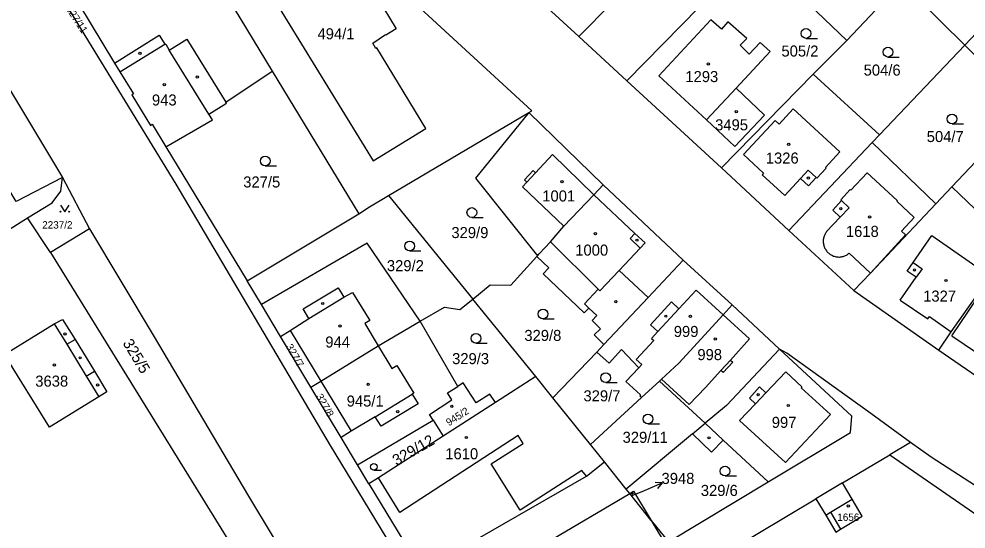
# Model space of a CAD drawing. Extents: x -679220 to -673243, y -1075091 to -1066557.
# Drawn here: x -675968.3 to -675822.7, y -1072251.7 to -1072173.3 of the extents above; entities that cross this region are included whole.
import ezdxf

# ---------------------------------------------------------------- set-up
doc = ezdxf.new("R2010")
doc.units = 0
for name, color, linetype in [('Hranice parcel', 7, 'Continuous'), ('Parcelní čísla', 7, 'Continuous'), ('Pop  PČ popisy', 7, 'Continuous'), ('Vnitřní kresba', 7, 'Continuous'), ('Značky budov', 7, 'Continuous'), ('Značky kultur', 7, 'Continuous')]:
    doc.layers.add(name, color=color, linetype=linetype)

msp = doc.modelspace()

# ---------------------------------------------------------------- linework, layer by layer
at = {"layer": 'Hranice parcel'}
for p, q in [((-675822.87, -1072177.31), (-675804.14, -1072157.36)), ((-675841, -1072176.55), (-675855.42, -1072162.79)), ((-675938.85, -1072165.67), (-675929.38, -1072181.3)), ((-675832.59, -1072167.65), (-675841, -1072176.55)), ((-675832.59, -1072167.65), (-675822.87, -1072177.31)), ((-675882.2, -1072175.96), (-675877.17, -1072170.82)), ((-675882.2, -1072175.96), (-675874.86, -1072182.77)), ((-675841, -1072176.55), (-675846.2, -1072181.74)), ((-675835.96, -1072191.08), (-675822.87, -1072177.31)), ((-675822.87, -1072177.31), (-675813.23, -1072186.76)), ((-675929.38, -1072181.3), (-675916.07, -1072203.21)), ((-675846.2, -1072181.74), (-675860.28, -1072196.18)), ((-675835.96, -1072191.08), (-675846.2, -1072181.74)), ((-675874.86, -1072182.77), (-675860.28, -1072196.18)), ((-675862.57, -1072188.76), (-675858.05, -1072183.92)), ((-675813.23, -1072186.76), (-675824.84, -1072199.06)), ((-675911.51, -1072200.39), (-675889.92, -1072187.67)), ((-675878.49, -1072198.75), (-675889.92, -1072187.67)), ((-675837.1, -1072192.28), (-675835.96, -1072191.08)), ((-675849.94, -1072205.78), (-675837.1, -1072192.28)), ((-675827.32, -1072201.69), (-675837.1, -1072192.28)), ((-675945.71, -1072192.93), (-675933.22, -1072213.55)), ((-675860.28, -1072196.18), (-675849.94, -1072205.78)), ((-675961.64, -1072197.66), (-675957.46, -1072205.54)), ((-675866.16, -1072210.38), (-675878.49, -1072198.75)), ((-675824.84, -1072199.06), (-675827.32, -1072201.69)), ((-675911.51, -1072200.39), (-675898.53, -1072216.33)), ((-676000.77, -1072224.76), (-675966.99, -1072203.87)), ((-675963.46, -1072209.2), (-675966.99, -1072203.87)), ((-675933.22, -1072213.55), (-675916.07, -1072203.21)), ((-675957.46, -1072205.54), (-675963.46, -1072209.2)), ((-675849.94, -1072205.78), (-675839.95, -1072215.04)), ((-675963.46, -1072209.2), (-675930.36, -1072262.74)), ((-675888.7, -1072209.8), (-675888.59, -1072209.68)), ((-675888.7, -1072209.8), (-675886.82, -1072211.51)), ((-675858.63, -1072217.23), (-675866.16, -1072210.38)), ((-675931.04, -1072217.19), (-675933.22, -1072213.55)), ((-675839.95, -1072215.04), (-675826.88, -1072224.19)), ((-675928.1, -1072222.1), (-675931.04, -1072217.19)), ((-675888.81, -1072228.27), (-675898.53, -1072216.33)), ((-675851.38, -1072224.03), (-675858.63, -1072217.23)), ((-675900.85, -1072229.77), (-675906.6, -1072219.76)), ((-675923.45, -1072229.88), (-675928.1, -1072222.1)), ((-675879.87, -1072221.83), (-675878.36, -1072223.31)), ((-675879.46, -1072224.48), (-675886.22, -1072231.53)), ((-675878.36, -1072223.31), (-675879.46, -1072224.48)), ((-675826.88, -1072224.19), (-675815.27, -1072232.21)), ((-675923.45, -1072229.88), (-675921.9, -1072228.94)), ((-675888.81, -1072228.27), (-675895.05, -1072232.27)), ((-675886.22, -1072231.53), (-675888.81, -1072228.27)), ((-675869.79, -1072228.94), (-675872.57, -1072231.49)), ((-675862.79, -1072235.44), (-675869.79, -1072228.94)), ((-675918.79, -1072237.63), (-675923.45, -1072229.88)), ((-675880.45, -1072238.71), (-675886.22, -1072231.53)), ((-675872.57, -1072231.49), (-675880.45, -1072238.71)), ((-675872.85, -1072231.2), (-675872.57, -1072231.49)), ((-675895.05, -1072232.27), (-675903.06, -1072237.41)), ((-675916.25, -1072241.85), (-675904.63, -1072234.97)), ((-675904.63, -1072234.97), (-675903.06, -1072237.41)), ((-675864.76, -1072237.08), (-675862.79, -1072235.44)), ((-675916.25, -1072241.85), (-675918.79, -1072237.63)), ((-675864.76, -1072237.08), (-675874.93, -1072245.59)), ((-675878.25, -1072241.39), (-675880.45, -1072238.71)), ((-675831.19, -1072238.38), (-675834.37, -1072240.28)), ((-675841.66, -1072244.62), (-675834.37, -1072240.28)), ((-675834.37, -1072240.28), (-675799.8, -1072264.22)), ((-675914.5, -1072244.76), (-675916.25, -1072241.85)), ((-675874.93, -1072245.59), (-675878.25, -1072241.39)), ((-675914.5, -1072244.76), (-675906.36, -1072258.16)), ((-675868.44, -1072253.67), (-675853.09, -1072244.45)), ((-675841.66, -1072244.62), (-675845.76, -1072247.06)), ((-675874.39, -1072246.25), (-675874.93, -1072245.59)), ((-675871.11, -1072250.38), (-675874.39, -1072246.25)), ((-675895.24, -1072276.53), (-675845.76, -1072247.06)), ((-675871.11, -1072250.38), (-675868.44, -1072253.67)), ((-675871.11, -1072250.38), (-675868.96, -1072253.98))]:
    msp.add_line(p, q, dxfattribs=at)
for points in [[(-675990.34, -1072122.74), (-675965.06, -1072164.5), (-675944.22, -1072198.66), (-675920.45, -1072238.88), (-675899.68, -1072273.04), (-675879.13, -1072306.74), (-675849.47, -1072355.79), (-675790.19, -1072454.14)], [(-676002.04, -1072130.35), (-675984.64, -1072159.26), (-675978.83, -1072168.99), (-675961.64, -1072197.66)], [(-675961.64, -1072197.66), (-675968.73, -1072201.32), (-676008.59, -1072134.94)], [(-675889.92, -1072187.67), (-675889.47, -1072187.41), (-675911.07, -1072167.47), (-675923.12, -1072156.21)], [(-675895.7, -1072163.48), (-675887.06, -1072171.53), (-675882.2, -1072175.96)], [(-675855.42, -1072162.79), (-675863.71, -1072171.45), (-675874.86, -1072182.77)], [(-675959.18, -1072170.89), (-675953.64, -1072180.04), (-675952.8, -1072181.4), (-675950.72, -1072184.79), (-675950.97, -1072184.94), (-675948.1, -1072189.62), (-675947.84, -1072189.46), (-675945.71, -1072192.93)], [(-675858.05, -1072183.92), (-675852.79, -1072178.27), (-675854.31, -1072176.9), (-675856.05, -1072178.66), (-675857.43, -1072177.29), (-675856.4, -1072176.26), (-675859.3, -1072173.68), (-675860.3, -1072174.81), (-675861.92, -1072173.38), (-675869.92, -1072182), (-675862.57, -1072188.76)], [(-675945.71, -1072192.93), (-675938.56, -1072188.75), (-675939.11, -1072187.9), (-675936.39, -1072186.2), (-675936.49, -1072186.05), (-675929.38, -1072181.3)], [(-675858.05, -1072183.92), (-675853.68, -1072188.04), (-675858.25, -1072192.88), (-675862.57, -1072188.76)], [(-675889.92, -1072187.67), (-675898.1, -1072197.76), (-675888.59, -1072209.68)], [(-675966.99, -1072203.87), (-675963.2, -1072201.53), (-675961.87, -1072199.73), (-675961.64, -1072197.66)], [(-675888.59, -1072209.68), (-675888.34, -1072209.4), (-675886.57, -1072207.52), (-675884.51, -1072205.15), (-675879.91, -1072200.31), (-675878.49, -1072198.75)], [(-675811.2, -1072204.98), (-675812.84, -1072203.4), (-675816.48, -1072207.05), (-675824.84, -1072199.06)], [(-675916.07, -1072203.21), (-675914.43, -1072202.13), (-675911.51, -1072200.39)], [(-675827.32, -1072201.69), (-675837.36, -1072212.33), (-675839.95, -1072215.04)], [(-675957.46, -1072205.54), (-675947.66, -1072221.89), (-675933.02, -1072246.64), (-675925.29, -1072259.54)], [(-675906.6, -1072219.76), (-675914.77, -1072207.74), (-675931.04, -1072217.19)], [(-675826.88, -1072224.19), (-675824.97, -1072221.37), (-675819.4, -1072213.52), (-675817.52, -1072211.55), (-675814.73, -1072208.65)], [(-675898.53, -1072216.33), (-675895.85, -1072214.13), (-675892.66, -1072214.19), (-675888.7, -1072209.8)], [(-675886.82, -1072211.51), (-675887.68, -1072212.44), (-675881.42, -1072218.46), (-675880.68, -1072217.74), (-675879.45, -1072218.89), (-675880.16, -1072219.66), (-675878.91, -1072220.9), (-675879.87, -1072221.83)], [(-675866.16, -1072210.38), (-675871.56, -1072216.1), (-675878.36, -1072223.31)], [(-675906.6, -1072219.76), (-675902.88, -1072217.59), (-675900.52, -1072217.95), (-675898.53, -1072216.33)], [(-675858.63, -1072217.23), (-675860.02, -1072218.78), (-675866.83, -1072226.22), (-675869.49, -1072228.66), (-675869.79, -1072228.94)], [(-675963.64, -1072236.05), (-675970.54, -1072224.86), (-675962.89, -1072220.17), (-675961.65, -1072219.46), (-675959.69, -1072222.56), (-675956.72, -1072227.41), (-675954.82, -1072230.61), (-675956.06, -1072231.38), (-675963.64, -1072236.05)], [(-675921.9, -1072228.94), (-675913.06, -1072223.55), (-675906.6, -1072219.76)], [(-675928.1, -1072222.1), (-675926.62, -1072221.15), (-675921.9, -1072228.94)], [(-675879.46, -1072224.48), (-675877.58, -1072226.19), (-675875.64, -1072224.11), (-675873, -1072226.89), (-675874.99, -1072229.03)], [(-675851.38, -1072224.03), (-675859.52, -1072232.7), (-675862.79, -1072235.44)], [(-675853.09, -1072244.45), (-675840.42, -1072236.85), (-675840.26, -1072234.34), (-675851.38, -1072224.03)], [(-675831.19, -1072238.38), (-675837.34, -1072233.96), (-675850.24, -1072224.64), (-675851.38, -1072224.03)], [(-675921.9, -1072228.94), (-675917.21, -1072236.67), (-675918.79, -1072237.63)], [(-675874.99, -1072229.03), (-675872.73, -1072231.08), (-675872.85, -1072231.2)], [(-675904.63, -1072234.97), (-675905.21, -1072234.07), (-675901.74, -1072231.84), (-675902.42, -1072230.77), (-675900.85, -1072229.77)], [(-675895.05, -1072232.27), (-675895.9, -1072230.94), (-675898.02, -1072232.3), (-675900, -1072229.22), (-675900.85, -1072229.77)], [(-675903.06, -1072237.41), (-675913.02, -1072243.81), (-675914.5, -1072244.76)], [(-675853.09, -1072244.45), (-675860.01, -1072238.02), (-675861.81, -1072239.9), (-675864.76, -1072237.08)], [(-675675.24, -1072344.8), (-675677.06, -1072343.56), (-675675.65, -1072341.45), (-675809.62, -1072248.86), (-675810.47, -1072252.39), (-675814.41, -1072249.48), (-675828.02, -1072240.66), (-675831.19, -1072238.38)], [(-675906.36, -1072258.16), (-675881.04, -1072243.59), (-675878.25, -1072241.39)], [(-675845.76, -1072247.06), (-675844.26, -1072249.58), (-675842.72, -1072252.17), (-675841.96, -1072251.71), (-675838.63, -1072249.72), (-675840.17, -1072247.13), (-675841.66, -1072244.62)], [(-675891.17, -1072267.15), (-675896.13, -1072258.79), (-675887.39, -1072253.59), (-675887.24, -1072253.85), (-675874.39, -1072246.25)], [(-675874.39, -1072246.25), (-675873.79, -1072245.89), (-675871.11, -1072250.38)]]:
    msp.add_lwpolyline(points, dxfattribs=at)
at = {"layer": 'Pop  PČ popisy'}
for p, q in [((-675872.14, -1072245.77), (-675869.38, -1072244.6)), ((-675869.38, -1072244.6), (-675870.49, -1072244.53)), ((-675869.38, -1072244.6), (-675870.1, -1072245.45)), ((-675874.01, -1072246.56), (-675872.14, -1072245.77))]:
    msp.add_line(p, q, dxfattribs=at)
at = {"layer": 'Vnitřní kresba'}
for p, q in [((-675933.75, -1072162.6), (-675913.85, -1072195.08)), ((-675913.98, -1072168.74), (-675910.32, -1072174.79)), ((-675910.32, -1072174.79), (-675911.92, -1072175.76)), ((-675953.64, -1072180.04), (-675946.76, -1072175.76)), ((-675946.76, -1072175.76), (-675945.91, -1072177.12)), ((-675945.24, -1072178.06), (-675942.52, -1072176.37)), ((-675942.52, -1072176.37), (-675936.49, -1072186.05)), ((-675913.91, -1072177), (-675911.97, -1072175.67)), ((-675911.97, -1072175.67), (-675911.92, -1072175.76)), ((-675952.8, -1072181.4), (-675945.91, -1072177.12)), ((-675945.91, -1072177.12), (-675945.75, -1072177.12)), ((-675945.75, -1072177.12), (-675945.24, -1072178.06)), ((-675939.11, -1072187.9), (-675945.24, -1072178.06)), ((-675913.42, -1072177.8), (-675913.91, -1072177)), ((-675913.29, -1072177.72), (-675913.42, -1072177.8)), ((-675905.74, -1072190.13), (-675913.29, -1072177.72)), ((-675851.43, -1072189.43), (-675849.24, -1072187.07)), ((-675849.24, -1072187.07), (-675842.08, -1072193.69)), ((-675856.92, -1072194.12), (-675852.05, -1072188.85)), ((-675852.05, -1072188.85), (-675851.43, -1072189.43)), ((-675913.85, -1072195.08), (-675905.74, -1072190.13)), ((-675844.29, -1072196.09), (-675842.08, -1072193.69)), ((-675888.88, -1072196.9), (-675886.26, -1072194.1)), ((-675886.26, -1072194.1), (-675879.91, -1072200.31)), ((-675856.92, -1072194.12), (-675853.82, -1072197)), ((-675890.59, -1072198.01), (-675889.24, -1072196.57)), ((-675888.88, -1072196.9), (-675890.23, -1072198.35)), ((-675889.24, -1072196.57), (-675888.88, -1072196.9)), ((-675853.82, -1072197), (-675854.02, -1072197.22)), ((-675848.12, -1072197.78), (-675846.94, -1072196.5)), ((-675846.94, -1072196.5), (-675845.71, -1072197.62)), ((-675845.6, -1072197.73), (-675844.18, -1072196.19)), ((-675844.18, -1072196.19), (-675844.29, -1072196.09)), ((-675840.37, -1072199.59), (-675837.87, -1072196.94)), ((-675837.87, -1072196.94), (-675833.24, -1072201.19)), ((-675890.9, -1072199.07), (-675890.23, -1072198.35)), ((-675890.23, -1072198.35), (-675890.59, -1072198.01)), ((-675854.02, -1072197.22), (-675850.56, -1072200.43)), ((-675850.56, -1072200.43), (-675848.12, -1072197.78)), ((-675848.12, -1072197.78), (-675846.89, -1072198.91)), ((-675846.89, -1072198.91), (-675845.71, -1072197.62)), ((-675845.71, -1072197.62), (-675845.6, -1072197.73)), ((-675884.51, -1072205.15), (-675890.9, -1072199.07)), ((-675841.95, -1072201.09), (-675840.48, -1072199.49)), ((-675840.48, -1072199.49), (-675840.37, -1072199.59)), ((-675873.6, -1072206.25), (-675879.91, -1072200.31)), ((-675843.17, -1072202.65), (-675841.84, -1072201.2)), ((-675841.84, -1072201.2), (-675841.95, -1072201.09)), ((-675841.84, -1072201.2), (-675840.65, -1072202.29)), ((-675833.24, -1072201.19), (-675833.34, -1072201.3)), ((-675833.34, -1072201.3), (-675830.65, -1072203.77)), ((-675842.02, -1072203.75), (-675843.17, -1072202.65)), ((-675840.65, -1072202.29), (-675842.02, -1072203.75)), ((-675844.11, -1072205.97), (-675842.02, -1072203.75)), ((-675830.65, -1072203.77), (-675832.61, -1072205.9)), ((-675873.6, -1072206.25), (-675874.35, -1072207.04)), ((-675874.35, -1072207.04), (-675872.78, -1072208.52)), ((-675872.02, -1072207.71), (-675873.6, -1072206.25)), ((-675831.98, -1072206.48), (-675837.36, -1072212.33)), ((-675832.61, -1072205.9), (-675831.98, -1072206.48)), ((-675830.81, -1072210.71), (-675827.91, -1072206.55)), ((-675827.91, -1072206.55), (-675818.97, -1072212.84)), ((-675886.57, -1072207.52), (-675879.24, -1072214.82)), ((-675876.02, -1072211.95), (-675872.78, -1072208.52)), ((-675872.78, -1072208.52), (-675872.02, -1072207.71)), ((-675840.63, -1072209.26), (-675837.36, -1072212.33)), ((-675831.71, -1072212.03), (-675830.81, -1072210.71)), ((-675830.81, -1072210.71), (-675829.44, -1072211.67)), ((-675878.98, -1072215.06), (-675876.02, -1072211.95)), ((-675876.02, -1072211.95), (-675871.56, -1072216.1)), ((-675832.81, -1072216.51), (-675830.35, -1072212.98)), ((-675830.35, -1072212.98), (-675831.71, -1072212.03)), ((-675829.44, -1072211.67), (-675830.35, -1072212.98)), ((-675824.84, -1072221.97), (-675819.63, -1072214.25)), ((-675924.63, -1072217.85), (-675919.22, -1072214.61)), ((-675919.22, -1072214.61), (-675918.35, -1072216.07)), ((-675918.35, -1072216.07), (-675917.04, -1072215.34)), ((-675917.04, -1072215.34), (-675914.38, -1072219.62)), ((-675879.24, -1072214.82), (-675881.37, -1072217.07)), ((-675879.24, -1072214.82), (-675878.98, -1072215.06)), ((-675864.19, -1072214.97), (-675866.83, -1072217.83)), ((-675860.02, -1072218.78), (-675864.19, -1072214.97)), ((-675923.76, -1072219.31), (-675918.35, -1072216.07)), ((-675881.37, -1072217.07), (-675880.68, -1072217.74)), ((-675867.97, -1072216.77), (-675871.21, -1072220.3)), ((-675866.83, -1072217.83), (-675867.97, -1072216.77)), ((-675832.81, -1072216.51), (-675828.54, -1072219.38)), ((-675923.76, -1072219.31), (-675924.63, -1072217.85)), ((-675870.08, -1072221.35), (-675866.83, -1072217.83)), ((-675860.02, -1072218.78), (-675855.97, -1072222.48)), ((-675962.89, -1072220.17), (-675960.97, -1072223.3)), ((-675926.62, -1072221.15), (-675923.76, -1072219.31)), ((-675914.38, -1072219.62), (-675915.15, -1072220.09)), ((-675915.15, -1072220.09), (-675913.06, -1072223.55)), ((-675871.21, -1072220.3), (-675870.08, -1072221.35)), ((-675828.54, -1072219.38), (-675828.29, -1072219.03)), ((-675828.29, -1072219.03), (-675824.97, -1072221.37)), ((-675870.08, -1072221.35), (-675871.03, -1072222.38)), ((-675960.97, -1072223.3), (-675959.69, -1072222.56)), ((-675870.69, -1072222.69), (-675873.39, -1072225.62)), ((-675871.03, -1072222.38), (-675870.69, -1072222.69)), ((-675855.97, -1072222.48), (-675858.91, -1072225.72)), ((-675824.84, -1072221.97), (-675816.78, -1072227.53)), ((-675960.97, -1072223.3), (-675958.01, -1072228.2)), ((-675913.06, -1072223.55), (-675910.97, -1072227.02)), ((-675873.39, -1072225.62), (-675872.55, -1072226.4)), ((-675860.37, -1072227.33), (-675858.91, -1072225.72)), ((-675858.55, -1072226.04), (-675860.01, -1072227.65)), ((-675858.91, -1072225.72), (-675858.55, -1072226.04)), ((-675958.01, -1072228.2), (-675956.72, -1072227.41)), ((-675910.97, -1072227.02), (-675910.2, -1072226.55)), ((-675910.2, -1072226.55), (-675907.61, -1072230.83)), ((-675872.55, -1072226.4), (-675873, -1072226.89)), ((-675860.37, -1072227.33), (-675862.74, -1072229.95)), ((-675860.01, -1072227.65), (-675860.37, -1072227.33)), ((-675853.48, -1072230.78), (-675850.4, -1072227.52)), ((-675850.4, -1072227.52), (-675847.93, -1072229.86)), ((-675958.01, -1072228.2), (-675956.06, -1072231.38)), ((-675865.24, -1072232.55), (-675869.49, -1072228.66)), ((-675862.74, -1072229.95), (-675865.24, -1072232.55)), ((-675855.98, -1072231.6), (-675854.46, -1072229.85)), ((-675854.46, -1072229.85), (-675853.48, -1072230.78)), ((-675847.93, -1072229.86), (-675848.03, -1072229.97)), ((-675848.03, -1072229.97), (-675843.54, -1072234.08)), ((-675913.52, -1072234.43), (-675907.84, -1072230.97)), ((-675907.61, -1072230.83), (-675907.84, -1072230.97)), ((-675907.84, -1072230.97), (-675906.95, -1072232.44)), ((-675855.06, -1072232.46), (-675855.98, -1072231.6)), ((-675853.48, -1072230.78), (-675855.06, -1072232.46)), ((-675906.95, -1072232.44), (-675912.63, -1072235.89)), ((-675857.49, -1072235.03), (-675855.06, -1072232.46)), ((-675913.52, -1072234.43), (-675917.21, -1072236.67)), ((-675912.63, -1072235.89), (-675913.52, -1072234.43)), ((-675843.54, -1072234.08), (-675850.42, -1072241.5)), ((-675862.79, -1072235.44), (-675860.01, -1072238.02)), ((-675850.42, -1072241.5), (-675857.49, -1072235.03)), ((-675891.55, -1072237.31), (-675909.77, -1072249.14)), ((-675890.77, -1072238.53), (-675891.55, -1072237.31)), ((-675895.69, -1072241.69), (-675890.77, -1072238.53)), ((-675891.22, -1072248.79), (-675895.69, -1072241.69)), ((-675881.77, -1072242.69), (-675891.22, -1072248.79)), ((-675881.04, -1072243.59), (-675881.77, -1072242.69)), ((-675909.77, -1072249.14), (-675913.02, -1072243.81)), ((-675843.5, -1072249.12), (-675840.17, -1072247.13)), ((-675844.26, -1072249.58), (-675843.5, -1072249.12)), ((-675843.5, -1072249.12), (-675841.96, -1072251.71))]:
    msp.add_line(p, q, dxfattribs=at)
msp.add_lwpolyline([(-675844.11, -1072205.97), (-675844.19, -1072206.08), (-675844.27, -1072206.19), (-675844.34, -1072206.31), (-675844.4, -1072206.44), (-675844.46, -1072206.56), (-675844.5, -1072206.69), (-675844.54, -1072206.82), (-675844.58, -1072206.95), (-675844.6, -1072207.09), (-675844.62, -1072207.22), (-675844.63, -1072207.36), (-675844.63, -1072207.5), (-675844.62, -1072207.64), (-675844.61, -1072207.77), (-675844.59, -1072207.91), (-675844.56, -1072208.04), (-675844.52, -1072208.17), (-675844.48, -1072208.3), (-675844.43, -1072208.43), (-675844.37, -1072208.56), (-675844.3, -1072208.68), (-675844.23, -1072208.79), (-675844.15, -1072208.9), (-675844.07, -1072209.01), (-675843.98, -1072209.11), (-675843.88, -1072209.21), (-675843.78, -1072209.3), (-675843.67, -1072209.39), (-675843.56, -1072209.47), (-675843.44, -1072209.54), (-675843.32, -1072209.6), (-675843.2, -1072209.66), (-675843.07, -1072209.72), (-675842.94, -1072209.76), (-675842.81, -1072209.8), (-675842.67, -1072209.83), (-675842.54, -1072209.85), (-675842.4, -1072209.86), (-675842.26, -1072209.87), (-675842.13, -1072209.87), (-675841.99, -1072209.86), (-675841.85, -1072209.84), (-675841.72, -1072209.81), (-675841.59, -1072209.78), (-675841.46, -1072209.74), (-675841.33, -1072209.69), (-675841.2, -1072209.64), (-675841.08, -1072209.57), (-675840.96, -1072209.51), (-675840.85, -1072209.43), (-675840.73, -1072209.35), (-675840.63, -1072209.26)], dxfattribs=at)
at = {"layer": 'Značky budov'}
for centre, radius in [((-675949.71, -1072178.54), 0.175), ((-675862.3, -1072180.18), 0.175), ((-675940.91, -1072182.2), 0.175), ((-675945.97, -1072183.37), 0.175), ((-675858.01, -1072187.5), 0.175), ((-675849.95, -1072192.56), 0.175), ((-675884.82, -1072198.27), 0.175), ((-675846.91, -1072197.72), 0.175), ((-675841.93, -1072202.45), 0.175), ((-675837.5, -1072203.71), 0.175), ((-675879.67, -1072206.28), 0.175), ((-675873.29, -1072207.28), 0.175), ((-675830.6, -1072211.86), 0.175), ((-675825.75, -1072213.48), 0.175), ((-675921.61, -1072217.02), 0.175), ((-675876.53, -1072216.75), 0.175), ((-675868.84, -1072218.97), 0.175), ((-675865.06, -1072219.01), 0.175), ((-675918.96, -1072220.48), 0.175), ((-675961.22, -1072221.7), 0.175), ((-675861.23, -1072222.49), 0.175), ((-675958.91, -1072225.38), 0.175), ((-675962.88, -1072226.46), 0.175), ((-675956.22, -1072229.55), 0.175), ((-675914.62, -1072229.46), 0.175), ((-675854.64, -1072231.03), 0.175), ((-675901.75, -1072232.84), 0.175), ((-675850.02, -1072232.71), 0.175), ((-675910.06, -1072233.65), 0.175), ((-675899.5, -1072237.63), 0.175), ((-675862.19, -1072237.68), 0.175), ((-675873.98, -1072246.24), 0.117), ((-675840.79, -1072248.16), 0.175)]:
    msp.add_circle(centre, radius, dxfattribs=at)
at = {"layer": 'Značky kultur'}
for p, q in [((-675847.28, -1072176.24), (-675845.53, -1072176.24)), ((-675834.69, -1072179.11), (-675832.94, -1072179.11)), ((-675824.83, -1072189.39), (-675823.08, -1072189.39)), ((-675930.45, -1072195.84), (-675928.7, -1072195.84)), ((-675898.67, -1072203.78), (-675896.92, -1072203.78)), ((-675908.25, -1072208.93), (-675906.5, -1072208.93)), ((-675887.74, -1072219.38), (-675885.99, -1072219.38)), ((-675898.05, -1072223.13), (-675896.3, -1072223.13)), ((-675878.09, -1072229.19), (-675876.34, -1072229.19)), ((-675871.59, -1072235.54), (-675869.84, -1072235.54)), ((-675913.73, -1072242.64), (-675912.56, -1072242.64)), ((-675859.74, -1072243.55), (-675857.99, -1072243.55))]:
    msp.add_line(p, q, dxfattribs=at)
msp.add_lwpolyline([(-675961.92, -1072201.89), (-675961.25, -1072202.9), (-675960.58, -1072201.89)], dxfattribs=at)
for centre, radius in [((-675847.28, -1072175.49), 0.75), ((-675834.69, -1072178.36), 0.75), ((-675824.83, -1072188.64), 0.75), ((-675930.45, -1072195.09), 0.75), ((-675961.92, -1072202.9), 0.067), ((-675960.58, -1072202.9), 0.067), ((-675898.67, -1072203.03), 0.75), ((-675908.25, -1072208.18), 0.75), ((-675887.74, -1072218.63), 0.75), ((-675898.05, -1072222.38), 0.75), ((-675878.09, -1072228.44), 0.75), ((-675871.59, -1072234.79), 0.75), ((-675913.74, -1072242.14), 0.502), ((-675859.74, -1072242.8), 0.75)]:
    msp.add_circle(centre, radius, dxfattribs=at)

# ---------------------------------------------------------------- texts
at = {"layer": 'Parcelní čísla'}
for s, height, rotation, p in [('327/11', 1.14, 303, (-675961.17, -1072171.68)), ('325/5', 1.7, 301, (-675952.43, -1072223.09)), ('327/7', 1.14, 300, (-675927.32, -1072223.65)), ('327/8', 1.14, 300, (-675922.7, -1072231.3)), ('945/2', 1.14, 33, (-675902.19, -1072235.92)), ('329/12', 1.7, 30, (-675910.27, -1072242.03))]:
    msp.add_text(s, height=height, rotation=rotation, dxfattribs=at).set_placement(p)
for s, height, p in [('494/1', 1.7, (-675922.41, -1072176.39)), ('505/2', 1.7, (-675851.06, -1072179.04)), ('504/6', 1.7, (-675838.42, -1072181.97)), ('1293', 1.7, (-675865.84, -1072182.97)), ('943', 1.7, (-675947.87, -1072186.57)), ('3495', 1.7, (-675861.26, -1072190.39)), ('504/7', 1.7, (-675828.72, -1072192.19)), ('1326', 1.7, (-675853.47, -1072195.5)), ('327/5', 1.7, (-675933.83, -1072199.18)), ('1001', 1.7, (-675887.84, -1072201.33)), ('2237/2', 1.14, (-675964.75, -1072205.5)), ('329/9', 1.7, (-675901.82, -1072206.96)), ('1618', 1.7, (-675841.15, -1072206.78)), ('1000', 1.7, (-675882.77, -1072209.66)), ('329/2', 1.7, (-675911.74, -1072212.05)), ('1327', 1.7, (-675829.27, -1072216.73)), ('329/8', 1.7, (-675890.6, -1072222.78)), ('999', 1.7, (-675867.62, -1072222.17)), ('944', 1.7, (-675921.21, -1072223.79)), ('329/3', 1.7, (-675901.71, -1072226.35)), ('998', 1.7, (-675863.99, -1072225.73)), ('3638', 1.7, (-675965.81, -1072229.81)), ('329/7', 1.7, (-675881.51, -1072232.07)), ('945/1', 1.7, (-675917.92, -1072232.87)), ('997', 1.7, (-675852.55, -1072236.15)), ('329/11', 1.7, (-675875.49, -1072238.45)), ('1610', 1.7, (-675902.76, -1072240.98)), ('3948', 1.7, (-675869.5, -1072244.77)), ('329/6', 1.7, (-675863.46, -1072246.62)), ('1656', 1.14, (-675842.47, -1072250.46))]:
    msp.add_text(s, height=height, dxfattribs=at).set_placement(p)

doc.saveas('drawing.dxf')
